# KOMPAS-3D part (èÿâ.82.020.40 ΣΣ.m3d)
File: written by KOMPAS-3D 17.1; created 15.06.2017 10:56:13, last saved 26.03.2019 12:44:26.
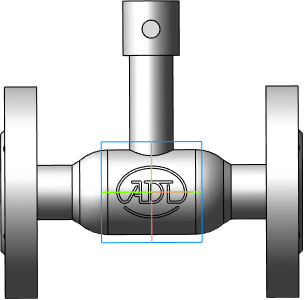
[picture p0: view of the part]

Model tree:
1. Операция без истории:2  (labels: Сталь 20  ГОСТ 1050-88)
